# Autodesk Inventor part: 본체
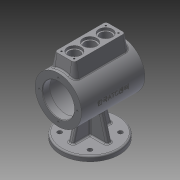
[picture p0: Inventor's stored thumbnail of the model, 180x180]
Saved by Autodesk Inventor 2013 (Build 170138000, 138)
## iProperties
Created: 2015-11
Part Number: 본체
Material: 일반
Document SubType Name: Modeling
Designer: mduedu
Density: 2.71 g/cm^3
Author: mduedu
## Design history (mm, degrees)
sketch "스케치2"
  geometry: C1 r 47.5 at (0, 0); 1 further point
  constraints: 1 centre point, 1 coincident
  dimensions: "d147" = 95 diameter of C1
extrude "돌출1" new body sketch "스케치2" stored distance "d12" = 130; taper "d13" = 0 deg
feature "쉘1" dims "d31" = 15, "d32" = 6, "d33" = 15
sketch "스케치5"
  geometry: C1 r 32.5 at (0, 0); 1 further point
  constraints: 1 centre point, 1 coincident
  dimensions: "d34" = 65 diameter of C1
extrude "돌출3" cut sketch "스케치5" stored distance "d36" = 3; taper "d37" = 0 deg
node "작업 평면1"
sketch "스케치6"
  geometry: L1 (-60, -55)-(60, -55); L2 (60, -55)-(60, 55); L3 (60, 55)-(-60, 55); L4 (-60, 55)-(-60, -55); L5 (-60, -55)-(60, 55); L6 (60, -55)-(-60, 55); C1 r 60 at (0, 0); 1 further point
  constraints: 12 end point, 2 midpoint, 2 parallel, 1 centre point, 1 coincident, 1 horizontal, 1 perpendicular
  dimensions: "d41" = 110 distance of L3.end L1.start; "d43" = 120 distance of L2.end L3.end; "d199" = 120 diameter of C1
extrude "돌출4" join sketch "스케치6" distance "d44" = 10; taper "d45" = 0 deg
sketch "스케치19"
  geometry: L1 (-5, 40)-(5, 40); L2 (5, 40)-(5, -40); L3 (5, -40)-(-5, -40); L4 (-5, -40)-(-5, 40); L5 (-60, 55)-(-60, -55) reference; L6 (5, -40)-(-5, 40); L7 (5, 40)-(-5, -40); 3 further points
  constraints: 12 end point, 2 midpoint, 2 parallel, 1 coincident, 1 horizontal, 1 horizontal alignment, 1 perpendicular
  dimensions: "d151" = 10 distance of L1.start L1.end; "d152" = 80 distance of L3.end L1.start
extrude "돌출9" join sketch "스케치19" stored distance "d153" = 10; taper "d154" = 0 deg
feature "면 기울기2" dims angle "d198" = 15 deg
sketch "스케치20"
  geometry: L1 (65, 32.5)-(50, 32.5) reference; L2 (50, 32.5)-(50, 41.5) reference; L3 (50, 41.5)-(-50, 41.5) reference; L4 (-50, 41.5)-(-50, 32.5) reference; L5 (-50, 32.5)-(-65, 32.5) reference; L6 (-65, 32.5)-(-65, 47.5) reference; L7 (-65, 47.5)-(65, 47.5) reference; L8 (65, 47.5)-(65, 32.5) reference; L9 (50, -32.5)-(65, -32.5) reference; L10 (65, -32.5)-(65, -47.5) reference; L11 (65, -47.5)-(5, -47.5) reference; L12 (5, -47.5)-(5, -90) reference; L13 (5, -90)-(60, -90) reference; L14 (60, -100)-(-60, -100) reference; L15 (-60, -90)-(-5, -90) reference; L16 (-5, -90)-(-5, -47.5) reference; L17 (-5, -47.5)-(-65, -47.5) reference; L18 (-65, -47.5)-(-65, -32.5) reference; L19 (-65, -32.5)-(-50, -32.5) reference; L20 (-50, -32.5)-(-50, -41.5) reference; L21 (-50, -41.5)-(50, -41.5) reference; L22 (50, -41.5)-(50, -32.5) reference; L23 (-40, -90)-(-28.612, -47.5); L24 (60, -90)-(60, -100) reference; L25 (-60, -100)-(-60, -90) reference; 1 further point
  constraints: 2 end point, 2 point on line
  dimensions: "d156" = 105 deg angle of L23 L15; "d200" = 20 distance from line of L23.start L25
feature "리브2" sketch "스케치20" dims "d157" = 1, "d158" = 10, "d159" = 0, "d160" = 0, "d161" = 1, "d162" = 1
fillet "모깎기21" dims "d163" = 3
fillet "모깎기22" dims "d164" = 3
fillet "모깎기23" dims "d165" = 3
sketch "스케치21" dims "d166" = 78
  geometry: 3 further points
  constraints: 2 horizontal alignment, 1 coincident, 2 other
hole "구멍6" sketch "스케치21" at (39, 0) diameter "d168" = 3.242; stored, may be unused: countersink angle "d172" = 90 deg, drill point angle "d174" = 118 deg; dims "d169" = 9, "d170" = 4, "d171" = 2, "d173" = 11
node "작업 평면2"
sketch "스케치13"
  geometry: L1 (-52.5, -20)-(52.5, -20); L2 (52.5, -20)-(52.5, 20); L3 (52.5, 20)-(-52.5, 20); L4 (-52.5, 20)-(-52.5, -20); L5 (-52.5, -20)-(52.5, 20); L6 (52.5, -20)-(-52.5, 20); 1 further point
  constraints: 12 end point, 2 midpoint, 2 parallel, 1 horizontal, 1 perpendicular
  dimensions: "d93" = 105 distance of L2.end L3.end; "d95" = 40 distance of L1.end L2.end
extrude "돌출8" join sketch "스케치13" stored distance "d96" = 80; taper "d97" = 0 deg
fillet "모깎기15" dims "d98" = 5
feature "면 기울기1" dims angle "d178" = 10 deg
fillet "모깎기24" dims "d179" = 3
sketch "스케치14"
  geometry: L1 (-52.5, 15)-(-52.5, -15) reference; L2 (52.5, -15)-(52.5, 15) reference; L3 (-52.5, 0)-(52.5, 0); 4 further points
  constraints: 2 end point, 2 midpoint, 2 point on line, 1 coincident
  dimensions: "d100" = 32 distance of point (-32, 0) point (0, 0); "d102" = 32 distance of point (32, 0) point (0, 0) (derived)
hole "구멍3" sketch "스케치14" at (-32, 0), (0, 0), (32, 0) diameter "d103" = 22; stored, may be unused: countersink angle "d107" = 90 deg, drill point angle "d109" = 118 deg; dims "d104" = 8, "d105" = 28, "d106" = 5, "d108" = 10
sketch "스케치15"
  geometry: L1 (45.5, -13)-(-45.5, -13); L2 (-45.5, -13)-(-45.5, 13); L3 (-45.5, 13)-(45.5, 13); L4 (45.5, 13)-(45.5, -13); L5 (45.5, -13)-(-45.5, 13); L6 (-45.5, -13)-(45.5, 13); L7 (47.5, 20)-(-47.5, 20) reference; L8 (-52.5, 15)-(-52.5, -15) reference; 5 further points
  constraints: 12 end point, 4 coincident, 2 midpoint, 2 parallel, 1 horizontal, 1 perpendicular
  dimensions: "d110" = 7 distance between parallel lines of L3 L7; "d111" = 7 distance between parallel lines of L2 L8 (derived)
hole "구멍4" sketch "스케치15" at (-45.5, 13), (45.5, 13), (45.5, -13), (-45.5, -13) diameter "d112" = 3.242; stored, may be unused: countersink angle "d116" = 90 deg, drill point angle "d118" = 118 deg; dims "d113" = 10, "d114" = 28, "d115" = 5, "d117" = 13
node "작업 평면3"
chamfer "모따기2" distance "d183" = 1; stored, may be unused: second distance "d184" = 2, angle "d185" = 45 deg
fillet "모깎기26" dims "d194" = 3
sketch "스케치24"
  geometry: L1 (-31.113, -31.113)-(31.113, -31.113); L2 (31.113, -31.113)-(31.113, 31.113); L3 (31.113, 31.113)-(-31.113, 31.113); L4 (-31.113, 31.113)-(-31.113, -31.113); L5 (-31.113, -31.113)-(31.113, 31.113); L6 (31.113, -31.113)-(-31.113, 31.113); 1 further point
  constraints: 12 end point, 2 midpoint, 2 parallel, 2 perpendicular, 1 horizontal
  dimensions: "d201" = 88 distance of L1.start L2.end
hole "구멍8" sketch "스케치24" at (-31.113, -31.113), (31.113, 31.113), (31.113, -31.113), (-31.113, 31.113) diameter "d203" = 9; stored, may be unused: countersink angle "d207" = 90 deg, drill point angle "d209" = 118 deg; dims "d204" = 6, "d205" = 4, "d206" = 2, "d208" = 8
sketch "스케치22"
  geometry: 2 further points
  constraints: 1 coincident, 1 other
feature "엠보싱3" sketch "스케치22" dims "d31" = 15, "d93" = 105, "d95" = 40, "d181" = 0.5, "d182" = 0
node "솔리드1"
mirror "대칭6"
pattern_circular "원형 패턴2" dims angle "d176" = 360 deg
mirror "대칭5"
node "절단 모서리 투영1"
